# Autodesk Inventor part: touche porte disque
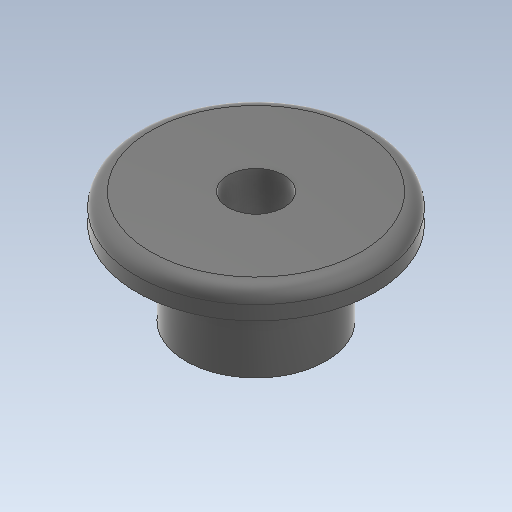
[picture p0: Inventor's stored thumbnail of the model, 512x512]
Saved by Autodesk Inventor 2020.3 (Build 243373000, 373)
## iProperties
Created: 2020-09
Part Number: touche porte disque
Material: Résine acétal, noir
Document SubType Name: Modeling
Designer: ficho
Density: 1.425 g/cm^3
Appearance: Lisse - Noir
Mass: 0.150038 g
Surface Area: 1.99406 cm^2
Volume: 0.10529 cm^3
Author: ficho
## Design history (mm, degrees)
sketch "Esquisse1"
  geometry: L1 (0, 0)-(4.25, 0); L2 (4.25, 0)-(4.25, 1); L3 (4.25, 1)-(1, 1); L4 (2.5, 0)-(0, 0); L5 (0, -1.854)-(0, -3); L6 (0, -3)-(2.5, -3); L7 (2.5, -3)-(2.5, 0); L8 (0, -1.854)-(1, -1.854); L9 (1, -1.854)-(1, 1)
  constraints: 18 end point, 3 parallel, 2 horizontal, 2 perpendicular, 1 point on line
  dimensions: "d0" = 2.5 distance between parallel lines of L5 L7; "d1" = 4.25 distance between parallel lines of L5 L2; "d2" = 3 distance between parallel lines of L1 L6; "d3" = 1 distance between parallel lines of L1 L3; "d4" = 1 distance between parallel lines of L9 L5
revolve "Révolution1" sketch "Esquisse1" stored, may be unused: angle "d5" = 90 deg
fillet "Congé1" dims "d6" = 0.5
node "Solide1"
